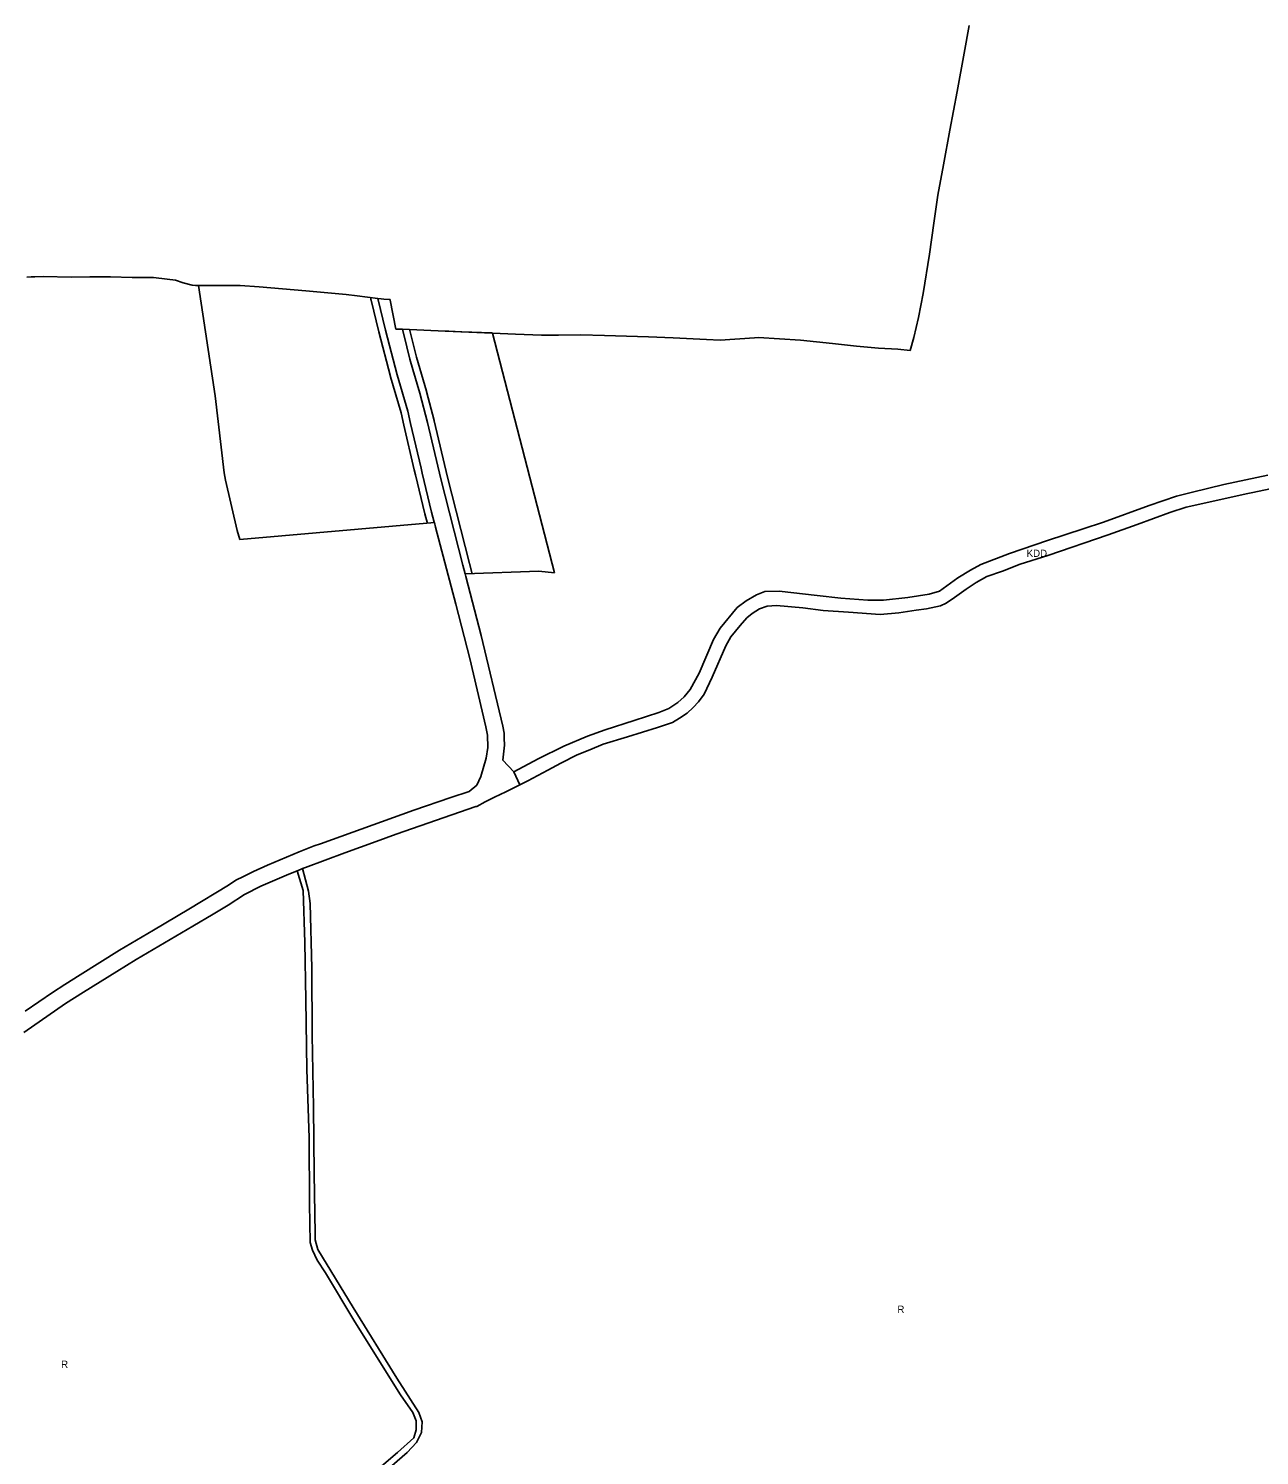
# Model space of a CAD drawing. Extents: x 7435758 to 7439981, y 5550649 to 5554049.
# Drawn here: x 7438071 to 7438957, y 5551818 to 5552845 of the extents above; entities that cross this region are included whole.
import ezdxf

# ---------------------------------------------------------------- set-up
doc = ezdxf.new("R2010")
doc.units = 0
for name, color, linetype in [('_Tereny_wyrok', 7, 'Continuous'), ('linie_rozgraniczające', 7, 'Continuous'), ('linie_zabudowy_nieprzekraczalne', 7, 'Continuous'), ('oznaczenia_przeznaczen', 7, 'Continuous')]:
    doc.layers.add(name, color=color, linetype=linetype)

msp = doc.modelspace()

# ---------------------------------------------------------------- linework, layer by layer
at = {"layer": '_Tereny_wyrok'}
for p, q in [((7438193.7, 5552660.4), (7438205.7, 5552581)), ((7438328.2, 5552628.3), (7438322.7, 5552651.1)), ((7438336.6, 5552596.2), (7438328.2, 5552628.3)), ((7438340.5, 5552628.9), (7438343.6, 5552616.4)), ((7438343.6, 5552616.4), (7438345.8, 5552607.5)), ((7438449.9, 5552453.6), (7438405.4, 5552626.2)), ((7438345.8, 5552607.5), (7438348, 5552600)), ((7438344.3, 5552570), (7438336.6, 5552596.2)), ((7438348, 5552600), (7438353.1, 5552582.9)), ((7438205.7, 5552581), (7438212.2, 5552525.6)), ((7438353.1, 5552582.9), (7438358.5, 5552561.9)), ((7438346.4, 5552561), (7438344.3, 5552570)), ((7438353.9, 5552528.9), (7438346.4, 5552561)), ((7438358.5, 5552561.9), (7438368, 5552521.2)), ((7438212.2, 5552525.6), (7438213.2, 5552520.4)), ((7438354.8, 5552525.3), (7438353.9, 5552528.9)), ((7438361.5, 5552497.4), (7438354.8, 5552525.3)), ((7438213.2, 5552520.4), (7438221.5, 5552484)), ((7438368, 5552521.2), (7438383.9, 5552459.1)), ((7438363.4, 5552490.2), (7438361.5, 5552497.4)), ((7438221.5, 5552484), (7438223.4, 5552477.5)), ((7438223.4, 5552477.5), (7438363.5, 5552489.8)), ((7438363.5, 5552489.8), (7438363.4, 5552490.2)), ((7438383.9, 5552459.1), (7438385.6, 5552452.8)), ((7438385.6, 5552452.8), (7438438.6, 5552454.9)), ((7438438.6, 5552454.9), (7438449.9, 5552453.6))]:
    msp.add_line(p, q, dxfattribs=at)
for points in [[(7438299.9, 5552654), (7438271, 5552656.6), (7438237.5, 5552659.5), (7438223.8, 5552660.4), (7438210.5, 5552660.5), (7438193.7, 5552660.4)], [(7438322.7, 5552651.1), (7438322.7, 5552651.1), (7438307.8, 5552653.1), (7438299.9, 5552654)], [(7438383.3, 5552627.1), (7438373.8, 5552627.5), (7438371.3, 5552627.6), (7438340.5, 5552628.9)], [(7438405.4, 5552626.2), (7438405.4, 5552626.2), (7438404.5, 5552626.3), (7438383.3, 5552627.1)]]:
    msp.add_lwpolyline(points, dxfattribs=at)
at = {"layer": 'linie_rozgraniczające'}
for p, q in [((7438744.7, 5552827.8), (7438748.3, 5552847.5)), ((7438739.6, 5552800), (7438744.7, 5552827.8)), ((7438734.4, 5552772.2), (7438739.6, 5552800)), ((7438729.7, 5552747.3), (7438734.4, 5552772.2)), ((7438725.8, 5552725.5), (7438729.7, 5552747.3)), ((7438722.9, 5552705.2), (7438725.8, 5552725.5)), ((7438719.7, 5552682.9), (7438722.9, 5552705.2)), ((7438715.2, 5552654.7), (7438719.7, 5552682.9)), ((7438070.2, 5552666.4), (7438073.3, 5552666.7)), ((7438073.3, 5552666.7), (7438076.1, 5552666.7)), ((7438076.1, 5552666.7), (7438081.9, 5552666.9)), ((7438081.9, 5552666.9), (7438102.5, 5552666.5)), ((7438102.5, 5552666.5), (7438115.5, 5552666.7)), ((7438115.5, 5552666.7), (7438127.8, 5552666.8)), ((7438127.8, 5552666.8), (7438130.4, 5552666.6)), ((7438130.4, 5552666.6), (7438146.1, 5552666.3)), ((7438146.1, 5552666.3), (7438161.3, 5552666.1)), ((7438161.3, 5552666.1), (7438171.2, 5552665)), ((7438171.2, 5552665), (7438177.1, 5552664.2)), ((7438177.1, 5552664.2), (7438182.8, 5552662.4)), ((7438182.8, 5552662.4), (7438189.1, 5552660.6)), ((7438189.1, 5552660.6), (7438191.6, 5552660.4)), ((7438191.6, 5552660.4), (7438192.8, 5552660.4)), ((7438193.7, 5552660.4), (7438205.7, 5552581)), ((7438322.7, 5552651.1), (7438328.2, 5552628.3)), ((7438322.7, 5552651.1), (7438325.3, 5552650.8)), ((7438325.3, 5552650.8), (7438327.2, 5552650.7)), ((7438327.2, 5552650.7), (7438331.6, 5552650.3)), ((7438331.6, 5552650.3), (7438331.7, 5552650)), ((7438331.7, 5552650), (7438335.8, 5552629.1)), ((7438711.7, 5552637.4), (7438715.2, 5552654.7)), ((7438708.5, 5552622.9), (7438711.7, 5552637.4)), ((7438328.2, 5552628.3), (7438336.6, 5552596.2)), ((7438335.8, 5552629.1), (7438337.2, 5552629)), ((7438337.2, 5552629), (7438340.2, 5552628.9)), ((7438340.2, 5552628.9), (7438340.5, 5552628.9)), ((7438343.6, 5552616.4), (7438340.5, 5552628.9)), ((7438345.8, 5552607.5), (7438343.6, 5552616.4)), ((7438449.9, 5552453.6), (7438405.4, 5552626.2)), ((7438421.9, 5552625.5), (7438440.6, 5552624.7)), ((7438440.6, 5552624.7), (7438452.7, 5552624.8)), ((7438452.7, 5552624.8), (7438468.8, 5552625)), ((7438468.8, 5552625), (7438485.8, 5552624.5)), ((7438485.8, 5552624.5), (7438517.5, 5552623.6)), ((7438517.5, 5552623.6), (7438535.2, 5552622.7)), ((7438535.2, 5552622.7), (7438559.2, 5552621.5)), ((7438559.2, 5552621.5), (7438569.2, 5552621)), ((7438569.2, 5552621), (7438593.7, 5552622.8)), ((7438593.7, 5552622.8), (7438596.6, 5552623)), ((7438596.6, 5552623), (7438626.9, 5552621)), ((7438626.9, 5552621), (7438650, 5552618.7)), ((7438650, 5552618.7), (7438667.2, 5552616.7)), ((7438667.2, 5552616.7), (7438683.1, 5552615.4)), ((7438705.8, 5552613.6), (7438708.5, 5552622.9)), ((7438348, 5552600), (7438345.8, 5552607.5)), ((7438683.1, 5552615.4), (7438697, 5552614.6)), ((7438697, 5552614.6), (7438705.8, 5552613.6)), ((7438336.6, 5552596.2), (7438344.3, 5552570)), ((7438353.1, 5552582.9), (7438348, 5552600)), ((7438348, 5552600), (7438348, 5552600)), ((7438205.7, 5552581), (7438212.2, 5552525.6)), ((7438358.5, 5552561.9), (7438353.1, 5552582.9)), ((7438344.3, 5552570), (7438346.4, 5552561)), ((7438346.4, 5552561), (7438353.9, 5552528.9)), ((7438368, 5552521.2), (7438358.5, 5552561.9)), ((7438212.2, 5552525.6), (7438213.2, 5552520.4)), ((7438353.9, 5552528.9), (7438354.8, 5552525.3)), ((7438354.8, 5552525.3), (7438361.5, 5552497.4)), ((7438963, 5552523.9), (7438931.4, 5552517.3)), ((7438213.2, 5552520.4), (7438221.5, 5552484)), ((7438383.9, 5552459.1), (7438368, 5552521.2)), ((7438931.4, 5552517.3), (7438909, 5552511.8)), ((7438951.1, 5552511.2), (7438970.6, 5552515.4)), ((7438897.4, 5552508.9), (7438877.7, 5552502)), ((7438909, 5552511.8), (7438897.4, 5552508.9)), ((7438904.3, 5552500.8), (7438924.9, 5552505.4)), ((7438924.9, 5552505.4), (7438947.5, 5552510.4)), ((7438947.5, 5552510.4), (7438951.1, 5552511.2)), ((7438361.5, 5552497.4), (7438363.4, 5552490.2)), ((7438877.7, 5552502), (7438844.9, 5552490)), ((7438869.1, 5552488.4), (7438892.7, 5552497.1)), ((7438892.7, 5552497.1), (7438904.3, 5552500.8)), ((7438221.5, 5552484), (7438223.4, 5552477.5)), ((7438223.4, 5552477.5), (7438363.5, 5552489.8)), ((7438363.4, 5552490.2), (7438363.5, 5552489.8)), ((7438363.5, 5552489.8), (7438364.3, 5552486.5)), ((7438364.3, 5552486.5), (7438379, 5552431.1)), ((7438830.2, 5552485.2), (7438804.6, 5552477)), ((7438844.9, 5552490), (7438830.2, 5552485.2)), ((7438848.2, 5552480.9), (7438869.1, 5552488.4)), ((7438804.6, 5552477), (7438777.3, 5552467.6)), ((7438804.9, 5552466.2), (7438848.2, 5552480.9)), ((7438777.3, 5552467.6), (7438756.7, 5552459.7)), ((7438785, 5552459.9), (7438804.9, 5552466.2)), ((7438385.6, 5552452.8), (7438383.9, 5552459.1)), ((7438385.6, 5552452.8), (7438438.6, 5552454.9)), ((7438386, 5552451), (7438385.6, 5552452.8)), ((7438438.6, 5552454.9), (7438449.9, 5552453.6)), ((7438749.3, 5552455.6), (7438740, 5552450)), ((7438756.7, 5552459.7), (7438749.3, 5552455.6)), ((7438761, 5552450.9), (7438772.1, 5552454.9)), ((7438772.1, 5552454.9), (7438785, 5552459.9)), ((7438397.2, 5552408.5), (7438386, 5552451)), ((7438740, 5552450), (7438726.8, 5552440.5)), ((7438737.8, 5552435.8), (7438746.1, 5552441.8)), ((7438746.1, 5552441.8), (7438753.2, 5552446.7)), ((7438753.2, 5552446.7), (7438761, 5552450.9)), ((7438587.9, 5552433.5), (7438581.2, 5552428.6)), ((7438595.2, 5552437.7), (7438587.9, 5552433.5)), ((7438601.2, 5552440.2), (7438595.2, 5552437.7)), ((7438611.6, 5552440.4), (7438601.2, 5552440.2)), ((7438638.9, 5552437.2), (7438611.6, 5552440.4)), ((7438656, 5552435.5), (7438638.9, 5552437.2)), ((7438675.4, 5552434), (7438656, 5552435.5)), ((7438686.6, 5552434), (7438675.4, 5552434)), ((7438704, 5552435.9), (7438686.6, 5552434)), ((7438719.5, 5552438.2), (7438704, 5552435.9)), ((7438726.8, 5552440.5), (7438719.5, 5552438.2)), ((7438727.5, 5552429.9), (7438731.7, 5552431.9)), ((7438731.7, 5552431.9), (7438737.8, 5552435.8)), ((7438379, 5552431.1), (7438388.9, 5552391.9)), ((7438581.2, 5552428.6), (7438569.1, 5552413.8)), ((7438583.5, 5552415.7), (7438588.2, 5552421.2)), ((7438588.2, 5552421.2), (7438592.1, 5552424.4)), ((7438592.1, 5552424.4), (7438597.3, 5552427.6)), ((7438597.3, 5552427.6), (7438602.9, 5552429.7)), ((7438602.9, 5552429.7), (7438609.7, 5552430.2)), ((7438609.7, 5552430.2), (7438628.6, 5552428.4)), ((7438628.6, 5552428.4), (7438643.1, 5552426.5)), ((7438643.1, 5552426.5), (7438661.4, 5552425.3)), ((7438661.4, 5552425.3), (7438684.2, 5552423.7)), ((7438684.2, 5552423.7), (7438697.6, 5552424.9)), ((7438697.6, 5552424.9), (7438710.2, 5552426.7)), ((7438710.2, 5552426.7), (7438717.6, 5552427.8)), ((7438717.6, 5552427.8), (7438727.5, 5552429.9)), ((7438569.1, 5552413.8), (7438564.2, 5552405.7)), ((7438576.8, 5552407.5), (7438583.5, 5552415.7)), ((7438412.7, 5552343.2), (7438397.2, 5552408.5)), ((7438564.2, 5552405.7), (7438554, 5552381.5)), ((7438563.3, 5552378.5), (7438573.2, 5552401.1)), ((7438573.2, 5552401.1), (7438576.8, 5552407.5)), ((7438388.9, 5552391.9), (7438400.5, 5552342.8)), ((7438554, 5552381.5), (7438547.5, 5552369.7)), ((7438547.5, 5552369.7), (7438543.2, 5552364.3)), ((7438557.5, 5552366.3), (7438563.3, 5552378.5)), ((7438538.7, 5552360.3), (7438532.2, 5552356)), ((7438543.2, 5552364.3), (7438538.7, 5552360.3)), ((7438549.7, 5552356.6), (7438553.5, 5552360.7)), ((7438553.5, 5552360.7), (7438557.5, 5552366.3)), ((7438525, 5552353), (7438507.1, 5552347.4)), ((7438532.2, 5552356), (7438525, 5552353)), ((7438534.7, 5552346), (7438539.9, 5552349.1)), ((7438539.9, 5552349.1), (7438545.4, 5552352.5)), ((7438545.4, 5552352.5), (7438549.7, 5552356.6)), ((7438400.5, 5552342.8), (7438401.8, 5552336.8)), ((7438413.7, 5552338.1), (7438412.7, 5552343.2)), ((7438486.3, 5552340.7), (7438473.7, 5552336.1)), ((7438507.1, 5552347.4), (7438486.3, 5552340.7)), ((7438502.4, 5552335.6), (7438523.9, 5552342.3)), ((7438523.9, 5552342.3), (7438534.7, 5552346)), ((7438401.8, 5552336.8), (7438402, 5552327.9)), ((7438412.7, 5552318.7), (7438414, 5552329.5)), ((7438413.8, 5552334.5), (7438413.7, 5552338.1)), ((7438414, 5552329.5), (7438413.8, 5552334.5)), ((7438456.6, 5552328.8), (7438438.1, 5552319.8)), ((7438473.7, 5552336.1), (7438456.6, 5552328.8)), ((7438475.4, 5552326.2), (7438485, 5552330.2)), ((7438485, 5552330.2), (7438502.4, 5552335.6)), ((7438400.8, 5552320.1), (7438397, 5552307.1)), ((7438402, 5552327.9), (7438400.8, 5552320.1)), ((7438420.7, 5552310.4), (7438412.7, 5552318.7)), ((7438438.1, 5552319.8), (7438420.7, 5552310.4)), ((7438454.4, 5552316.7), (7438466.3, 5552322.6)), ((7438466.3, 5552322.6), (7438475.4, 5552326.2)), ((7438420.7, 5552310.4), (7438424.9, 5552301)), ((7438430.7, 5552303.9), (7438445, 5552311.6)), ((7438445, 5552311.6), (7438454.4, 5552316.7)), ((7438394, 5552300.7), (7438388.5, 5552296.3)), ((7438397, 5552307.1), (7438394, 5552300.7)), ((7438415, 5552296), (7438424.9, 5552301)), ((7438424.9, 5552301), (7438430.7, 5552303.9)), ((7438375.4, 5552291.9), (7438348.6, 5552282.7)), ((7438388.5, 5552296.3), (7438375.4, 5552291.9)), ((7438394, 5552285.5), (7438400, 5552288.8)), ((7438400, 5552288.8), (7438406.7, 5552292.2)), ((7438406.7, 5552292.2), (7438415, 5552296)), ((7438348.6, 5552282.7), (7438281.6, 5552258.6)), ((7438335.9, 5552265.4), (7438393.4, 5552285.3)), ((7438393.4, 5552285.3), (7438393.5, 5552285.4)), ((7438393.5, 5552285.4), (7438394, 5552285.5)), ((7438277.1, 5552257), (7438266.3, 5552252.7)), ((7438281.6, 5552258.6), (7438277.1, 5552257)), ((7438277.1, 5552257), (7438277.1, 5552257)), ((7438299, 5552252.1), (7438321.5, 5552260.2)), ((7438321.5, 5552260.2), (7438335.9, 5552265.4)), ((7438252.5, 5552247.1), (7438243.5, 5552243.2)), ((7438266.3, 5552252.7), (7438252.5, 5552247.1)), ((7438270.7, 5552241.5), (7438299, 5552252.1)), ((7438233.3, 5552238.7), (7438226.1, 5552235.1)), ((7438243.5, 5552243.2), (7438233.3, 5552238.7)), ((7438257.1, 5552236), (7438264.7, 5552239.1)), ((7438265.1, 5552239.2), (7438264.7, 5552239.1)), ((7438264.7, 5552239.1), (7438269, 5552224.9)), ((7438268.7, 5552240.7), (7438265.1, 5552239.2)), ((7438268.7, 5552240.7), (7438270.7, 5552241.5)), ((7438273, 5552224.5), (7438268.7, 5552240.7)), ((7438215.4, 5552228.9), (7438186.9, 5552211.5)), ((7438220.7, 5552232.3), (7438215.4, 5552228.9)), ((7438226.1, 5552235.1), (7438220.7, 5552232.3)), ((7438226.9, 5552222), (7438238.6, 5552228)), ((7438238.6, 5552228), (7438257.1, 5552236)), ((7438215, 5552214.4), (7438226.9, 5552222)), ((7438269, 5552224.9), (7438270.3, 5552187.4)), ((7438274, 5552215.5), (7438273, 5552224.5)), ((7438186.9, 5552211.5), (7438161.3, 5552196.4)), ((7438189.7, 5552199.2), (7438204.4, 5552207.9)), ((7438204.4, 5552207.9), (7438215, 5552214.4)), ((7438275.2, 5552169.1), (7438274, 5552215.5)), ((7438161.3, 5552196.4), (7438137, 5552182.1)), ((7438149, 5552175.3), (7438189.7, 5552199.2)), ((7438270.3, 5552187.4), (7438271.1, 5552146.3)), ((7438137, 5552182.1), (7438108.7, 5552164.3)), ((7438134.9, 5552166.6), (7438149, 5552175.3)), ((7438108.7, 5552164.3), (7438097.6, 5552157.4)), ((7438111.1, 5552151.7), (7438134.9, 5552166.6)), ((7438275.6, 5552120.9), (7438275.2, 5552169.1)), ((7438097.6, 5552157.4), (7438088.6, 5552151.6)), ((7438088.6, 5552151.6), (7438069.1, 5552138.1)), ((7438098, 5552143.5), (7438111.1, 5552151.7)), ((7438271.1, 5552146.3), (7438271.8, 5552096.2)), ((7438068.2, 5552122.8), (7438098, 5552143.5)), ((7438276.4, 5552069), (7438275.6, 5552120.9)), ((7438271.8, 5552096.2), (7438273.4, 5552047)), ((7438277, 5552021.2), (7438276.4, 5552069)), ((7438273.4, 5552047), (7438273.6, 5551999.3)), ((7438277.6, 5551977.9), (7438277, 5552021.2)), ((7438273.6, 5551999.3), (7438274.2, 5551971.6)), ((7438274.2, 5551971.6), (7438275.7, 5551966.1)), ((7438277.6, 5551973.4), (7438277.6, 5551977.9)), ((7438279.7, 5551966.5), (7438277.6, 5551973.4)), ((7438275.7, 5551966.1), (7438279.1, 5551958.9)), ((7438279.1, 5551958.9), (7438285.2, 5551949.8)), ((7438305, 5551924.7), (7438279.7, 5551966.5)), ((7438285.2, 5551949.8), (7438306.3, 5551914.5)), ((7438336.4, 5551873.8), (7438305, 5551924.7)), ((7438306.3, 5551914.5), (7438339, 5551861.9)), ((7438352.3, 5551849.2), (7438336.4, 5551873.8)), ((7438339, 5551861.9), (7438347.9, 5551849.1)), ((7438347.9, 5551849.1), (7438350.3, 5551843.2)), ((7438354.7, 5551842.6), (7438352.3, 5551849.2)), ((7438350.4, 5551836.8), (7438348.8, 5551831)), ((7438350.3, 5551843.2), (7438350.4, 5551836.8)), ((7438354.1, 5551834.9), (7438354.7, 5551842.6)), ((7438348.8, 5551831), (7438337, 5551820.3)), ((7438344, 5551820.4), (7438350.6, 5551827.6)), ((7438350.6, 5551827.6), (7438354.1, 5551834.9)), ((7438294.2, 5551777.4), (7438344, 5551820.4)), ((7438337, 5551820.3), (7438323.7, 5551809.1))]:
    msp.add_line(p, q, dxfattribs=at)
for points in [[(7438192.8, 5552660.4), (7438193.7, 5552660.4), (7438210.5, 5552660.5), (7438223.8, 5552660.4), (7438237.5, 5552659.5), (7438271, 5552656.6), (7438299.9, 5552654), (7438307.8, 5552653.1), (7438322.7, 5552651.1)], [(7438340.5, 5552628.9), (7438371.3, 5552627.6), (7438405.4, 5552626.2), (7438421.9, 5552625.5)]]:
    msp.add_lwpolyline(points, dxfattribs=at)
at = {"layer": 'linie_zabudowy_nieprzekraczalne'}
for points in [[(7438358.5, 5552489.2), (7438356.7, 5552496.1), (7438356.7, 5552496.2), (7438349.9, 5552524.1), (7438349.9, 5552524.1), (7438349.9, 5552524.2), (7438349, 5552527.8), (7438341.6, 5552559.9), (7438339.5, 5552568.7), (7438331.8, 5552594.8), (7438331.8, 5552594.9), (7438323.4, 5552627), (7438323.4, 5552627.1), (7438323.4, 5552627.1), (7438317.9, 5552650), (7438317.9, 5552650), (7438317.8, 5552650.3), (7438317.8, 5552650.6), (7438317.7, 5552650.9), (7438317.7, 5552651.2), (7438317.7, 5552651.6), (7438317.8, 5552651.8)], [(7438345.6, 5552628.9), (7438350.6, 5552608.9), (7438357.9, 5552584.3), (7438357.9, 5552584.1), (7438363.4, 5552563.2), (7438363.4, 5552563.1), (7438363.4, 5552563.1), (7438372.9, 5552522.4), (7438388.7, 5552460.4), (7438390.7, 5552452.9)]]:
    msp.add_lwpolyline(points, dxfattribs=at)

# ---------------------------------------------------------------- texts
at = {"layer": 'oznaczenia_przeznaczen'}
for s, p in [('KDD', (7438789.6, 5552465.1)), ('R', (7438696.6, 5551920.9)), ('R', (7438094.9, 5551881.3))]:
    msp.add_text(s, height=5.2, dxfattribs=at).set_placement(p)

doc.saveas('drawing.dxf')
